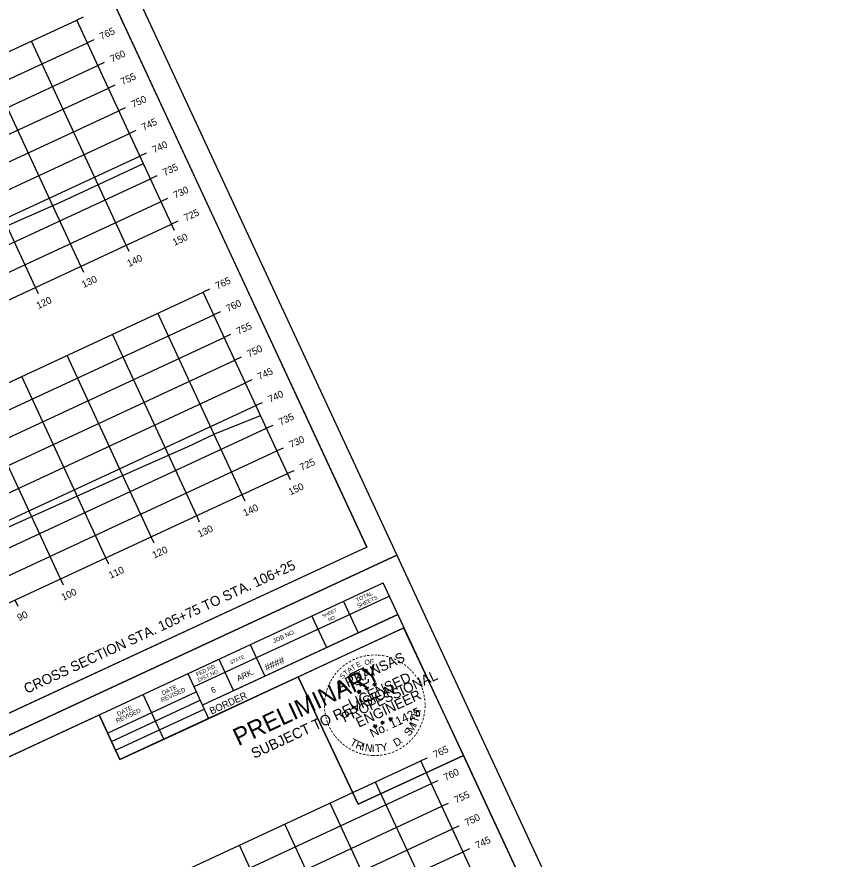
# Model space of a CAD drawing. Extents: x 1354696 to 1366163, y 660729 to 670380.
# Drawn here: x 1355461.4 to 1355627.1, y 664178.5 to 664346.9 of the extents above; entities that cross this region are included whole.
import ezdxf

# ---------------------------------------------------------------- set-up
doc = ezdxf.new("R2010")
doc.units = 0
for name, color, linetype in [('R_Axis', 7, 'Continuous'), ('R_Axis Annot', 7, 'Continuous'), ('R_Border', 7, 'Continuous'), ('R_Border PE', 7, 'Continuous'), ('R_Border Prem', 7, 'Continuous'), ('R_Draft', 7, 'Continuous'), ('R_Exist Surface', 7, 'Continuous'), ('R_Grid', 7, 'Continuous'), ('R_No Plot', 7, 'Continuous')]:
    doc.layers.add(name, color=color, linetype=linetype)

msp = doc.modelspace()

# ---------------------------------------------------------------- linework, layer by layer
at = {"layer": 'R_Axis'}
for p, q in [((1355474.6, 664346.89), (1355473.33, 664346.3)), ((1355492.28, 664305.49), (1355473.33, 664346.3)), ((1355476.71, 664342.36), (1355475.44, 664341.77)), ((1355478.81, 664337.82), (1355477.54, 664337.23)), ((1355480.92, 664333.29), (1355479.65, 664332.7)), ((1355483.02, 664328.75), (1355481.75, 664328.16)), ((1355485.13, 664324.22), (1355483.86, 664323.63)), ((1355487.23, 664319.68), (1355485.96, 664319.09)), ((1355489.34, 664315.15), (1355488.07, 664314.56)), ((1355491.45, 664310.61), (1355490.18, 664310.02)), ((1355493.55, 664306.07), (1355492.28, 664305.49)), ((1355220.18, 664179.15), (1355492.28, 664305.49)), ((1355492.87, 664304.22), (1355492.28, 664305.49)), ((1355483.8, 664300), (1355483.21, 664301.27)), ((1355474.73, 664295.79), (1355474.14, 664297.06)), ((1355465.66, 664291.58), (1355465.07, 664292.85)), ((1355499.87, 664292.47), (1355498.6, 664291.88)), ((1355515.44, 664255.6), (1355498.6, 664291.88)), ((1355501.97, 664287.93), (1355500.7, 664287.35)), ((1355504.08, 664283.4), (1355502.81, 664282.81)), ((1355506.18, 664278.86), (1355504.91, 664278.28)), ((1355508.29, 664274.33), (1355507.02, 664273.74)), ((1355510.4, 664269.79), (1355509.13, 664269.2)), ((1355512.5, 664265.26), (1355511.23, 664264.67)), ((1355514.61, 664260.72), (1355513.34, 664260.13)), ((1355243.34, 664129.27), (1355515.44, 664255.6)), ((1355516.71, 664256.19), (1355515.44, 664255.6)), ((1355516.03, 664254.33), (1355515.44, 664255.6)), ((1355506.96, 664250.12), (1355506.37, 664251.39)), ((1355497.89, 664245.91), (1355497.3, 664247.18)), ((1355488.82, 664241.7), (1355488.23, 664242.97)), ((1355479.75, 664237.49), (1355479.16, 664238.76)), ((1355470.68, 664233.27), (1355470.09, 664234.54)), ((1355461.61, 664229.06), (1355461.02, 664230.33)), ((1355543.38, 664198.74), (1355542.11, 664198.15)), ((1355558.96, 664161.87), (1355542.11, 664198.15)), ((1355545.49, 664194.21), (1355544.22, 664193.62)), ((1355547.59, 664189.67), (1355546.32, 664189.08)), ((1355549.7, 664185.14), (1355548.43, 664184.55)), ((1355551.81, 664180.6), (1355550.54, 664180.01))]:
    msp.add_line(p, q, dxfattribs=at)
at = {"layer": 'R_Border'}
for p, q in [((1355531.28, 664240.9), (1355444.76, 664427.26)), ((1355531.28, 664240.9), (1355244.5, 664107.76)), ((1355247.82, 664100.61), (1355534.6, 664233.76)), ((1355621.12, 664047.4), (1355534.6, 664233.76)), ((1355535.84, 664231.09), (1355496.75, 664212.94)), ((1355526.62, 664230.05), (1355529.54, 664223.76)), ((1355535.83, 664231.11), (1355535.83, 664231.11)), ((1355537.52, 664227.46), (1355498.43, 664209.31)), ((1355501.12, 664210.56), (1355537.52, 664227.46)), ((1355520.32, 664227.13), (1355523.25, 664220.84)), ((1355538.76, 664224.8), (1355481.95, 664198.42)), ((1355508.01, 664221.41), (1355510.93, 664215.12)), ((1355501.71, 664218.49), (1355504.63, 664212.19)), ((1355495.51, 664215.61), (1355499.67, 664206.65)), ((1355479.48, 664203.73), (1355497.2, 664211.96)), ((1355490.73, 664202.5), (1355486.57, 664211.46)), ((1355480.26, 664202.05), (1355497.98, 664210.28)), ((1355481.08, 664200.29), (1355498.8, 664208.52)), ((1355481.95, 664198.42), (1355477.79, 664207.38))]:
    msp.add_line(p, q, dxfattribs=at)
at = {"layer": 'R_Border PE'}
for p, q in [((1355532.52, 664213.35), (1355532.77, 664213.41)), ((1355532.52, 664213.35), (1355532.88, 664213.39)), ((1355532.52, 664213.35), (1355532.79, 664213.34)), ((1355532.88, 664213.39), (1355532.73, 664213.73)), ((1355532.73, 664213.73), (1355532.88, 664213.52)), ((1355532.73, 664213.73), (1355532.8, 664213.48)), ((1355532.81, 664213.03), (1355532.88, 664213.39)), ((1355532.81, 664213.03), (1355532.92, 664213.32)), ((1355532.81, 664213.03), (1355532.83, 664213.31)), ((1355533.15, 664213.64), (1355532.88, 664213.39)), ((1355533.2, 664213.21), (1355532.88, 664213.39)), ((1355533.15, 664213.64), (1355532.91, 664213.48)), ((1355533.2, 664213.21), (1355532.92, 664213.32)), ((1355533.2, 664213.21), (1355532.96, 664213.42)), ((1355533.15, 664213.64), (1355533.01, 664213.46)), ((1355529.4, 664211.91), (1355529.65, 664211.98)), ((1355529.4, 664211.91), (1355529.76, 664211.96)), ((1355529.4, 664211.91), (1355529.67, 664211.9)), ((1355529.76, 664211.96), (1355529.61, 664212.29)), ((1355529.61, 664212.29), (1355529.76, 664212.08)), ((1355529.61, 664212.29), (1355529.68, 664212.04)), ((1355529.69, 664211.6), (1355529.76, 664211.96)), ((1355529.69, 664211.6), (1355529.8, 664211.89)), ((1355529.69, 664211.6), (1355529.71, 664211.87)), ((1355530.03, 664212.21), (1355529.76, 664211.96)), ((1355530.08, 664211.78), (1355529.76, 664211.96)), ((1355530.03, 664212.21), (1355529.79, 664212.04)), ((1355530.08, 664211.78), (1355529.8, 664211.88)), ((1355530.08, 664211.78), (1355529.84, 664211.99)), ((1355530.03, 664212.21), (1355529.89, 664212.03)), ((1355530.92, 664212.62), (1355531.16, 664212.68)), ((1355530.92, 664212.62), (1355531.28, 664212.66)), ((1355530.92, 664212.62), (1355531.18, 664212.61)), ((1355531.28, 664212.66), (1355531.13, 664212.99)), ((1355531.13, 664212.99), (1355531.28, 664212.79)), ((1355531.13, 664212.99), (1355531.19, 664212.75)), ((1355531.21, 664212.3), (1355531.28, 664212.66)), ((1355531.21, 664212.3), (1355531.31, 664212.59)), ((1355531.21, 664212.3), (1355531.22, 664212.58)), ((1355531.55, 664212.91), (1355531.28, 664212.66)), ((1355531.6, 664212.48), (1355531.28, 664212.66)), ((1355531.55, 664212.91), (1355531.31, 664212.74)), ((1355531.6, 664212.48), (1355531.31, 664212.59)), ((1355531.6, 664212.48), (1355531.35, 664212.69)), ((1355531.55, 664212.91), (1355531.41, 664212.73)), ((1355535.71, 664206.48), (1355535.96, 664206.55)), ((1355535.71, 664206.48), (1355536.07, 664206.53)), ((1355535.71, 664206.48), (1355535.97, 664206.47)), ((1355536.07, 664206.53), (1355535.92, 664206.86)), ((1355535.92, 664206.86), (1355536.07, 664206.65)), ((1355535.92, 664206.86), (1355535.99, 664206.61)), ((1355536, 664206.17), (1355536.07, 664206.53)), ((1355536, 664206.17), (1355536.1, 664206.45)), ((1355536, 664206.17), (1355536.01, 664206.44)), ((1355536.34, 664206.77), (1355536.07, 664206.53)), ((1355536.39, 664206.35), (1355536.07, 664206.53)), ((1355536.34, 664206.77), (1355536.1, 664206.61)), ((1355536.39, 664206.35), (1355536.1, 664206.45)), ((1355536.39, 664206.35), (1355536.14, 664206.55)), ((1355536.34, 664206.77), (1355536.2, 664206.6)), ((1355532.59, 664205.04), (1355532.84, 664205.11)), ((1355532.59, 664205.04), (1355532.95, 664205.09)), ((1355532.59, 664205.04), (1355532.85, 664205.03)), ((1355532.95, 664205.09), (1355532.8, 664205.42)), ((1355532.8, 664205.42), (1355532.95, 664205.21)), ((1355532.8, 664205.42), (1355532.87, 664205.17)), ((1355532.88, 664204.73), (1355532.95, 664205.09)), ((1355532.88, 664204.73), (1355532.98, 664205.02)), ((1355532.88, 664204.73), (1355532.89, 664205)), ((1355533.22, 664205.34), (1355532.95, 664205.09)), ((1355533.27, 664204.91), (1355532.95, 664205.09)), ((1355533.22, 664205.34), (1355532.98, 664205.17)), ((1355533.27, 664204.91), (1355532.98, 664205.01)), ((1355533.27, 664204.91), (1355533.02, 664205.12)), ((1355533.22, 664205.34), (1355533.08, 664205.16)), ((1355534.1, 664205.75), (1355534.35, 664205.81)), ((1355534.1, 664205.75), (1355534.46, 664205.79)), ((1355534.1, 664205.75), (1355534.37, 664205.73)), ((1355534.46, 664205.79), (1355534.31, 664206.12)), ((1355534.31, 664206.12), (1355534.46, 664205.92)), ((1355534.31, 664206.12), (1355534.38, 664205.88)), ((1355534.39, 664205.43), (1355534.46, 664205.79)), ((1355534.39, 664205.43), (1355534.5, 664205.72)), ((1355534.39, 664205.43), (1355534.4, 664205.71)), ((1355534.73, 664206.04), (1355534.46, 664205.79)), ((1355534.78, 664205.61), (1355534.46, 664205.79)), ((1355534.73, 664206.04), (1355534.49, 664205.87)), ((1355534.78, 664205.61), (1355534.5, 664205.72)), ((1355534.78, 664205.61), (1355534.54, 664205.82)), ((1355534.73, 664206.04), (1355534.59, 664205.86))]:
    msp.add_line(p, q, dxfattribs=at)
for points in [[(1355531.38, 664216.09), (1355531.39, 664216.41), (1355530.78, 664216.1), (1355530.63, 664216.76), (1355527.81, 664215.45)], [(1355527.81, 664215.45), (1355528.4, 664214.81)], [(1355529.27, 664213.46), (1355529.31, 664213.38), (1355529.83, 664213.6), (1355529.98, 664213.15), (1355531.67, 664213.93), (1355531.63, 664214.5)], [(1355532.73, 664213.73), (1355533.2, 664213.21), (1355532.52, 664213.35), (1355533.15, 664213.64), (1355532.81, 664213.03), (1355532.73, 664213.73)], [(1355529.61, 664212.29), (1355530.08, 664211.78), (1355529.4, 664211.91), (1355530.03, 664212.21), (1355529.69, 664211.6), (1355529.61, 664212.29)], [(1355531.13, 664212.99), (1355531.6, 664212.48), (1355530.92, 664212.62), (1355531.55, 664212.91), (1355531.21, 664212.3), (1355531.13, 664212.99)], [(1355535.92, 664206.86), (1355536.39, 664206.35), (1355535.71, 664206.48), (1355536.34, 664206.77), (1355536, 664206.17), (1355535.92, 664206.86)], [(1355532.8, 664205.42), (1355533.27, 664204.91), (1355532.59, 664205.04), (1355533.22, 664205.34), (1355532.88, 664204.73), (1355532.8, 664205.42)], [(1355534.31, 664206.12), (1355534.78, 664205.61), (1355534.1, 664205.75), (1355534.73, 664206.04), (1355534.39, 664205.43), (1355534.31, 664206.12)]]:
    msp.add_lwpolyline(points, dxfattribs=at)
for centre, radius in [((1355532.88, 664213.39), 0.172), ((1355532.88, 664213.39), 0.145), ((1355532.88, 664213.39), 0.116), ((1355532.88, 664213.39), 0.0991), ((1355532.88, 664213.39), 0.0747), ((1355532.88, 664213.39), 0.0495), ((1355532.88, 664213.39), 0.0296), ((1355529.76, 664211.96), 0.172), ((1355529.76, 664211.96), 0.145), ((1355529.76, 664211.96), 0.116), ((1355529.76, 664211.96), 0.0991), ((1355529.76, 664211.96), 0.0747), ((1355529.76, 664211.96), 0.0495), ((1355529.76, 664211.96), 0.0296), ((1355531.28, 664212.66), 0.172), ((1355531.28, 664212.66), 0.145), ((1355531.28, 664212.66), 0.116), ((1355531.28, 664212.66), 0.0991), ((1355531.28, 664212.66), 0.0747), ((1355531.28, 664212.66), 0.0495), ((1355531.28, 664212.66), 0.0296), ((1355536.07, 664206.53), 0.172), ((1355536.07, 664206.53), 0.145), ((1355536.07, 664206.53), 0.116), ((1355536.07, 664206.53), 0.0991), ((1355536.07, 664206.53), 0.0747), ((1355536.07, 664206.53), 0.0495), ((1355536.07, 664206.53), 0.0296), ((1355532.95, 664205.09), 0.172), ((1355532.95, 664205.09), 0.145), ((1355532.95, 664205.09), 0.116), ((1355532.95, 664205.09), 0.0991), ((1355532.95, 664205.09), 0.0747), ((1355532.95, 664205.09), 0.0495), ((1355532.95, 664205.09), 0.0296), ((1355534.46, 664205.79), 0.172), ((1355534.46, 664205.79), 0.145), ((1355534.46, 664205.79), 0.116), ((1355534.46, 664205.79), 0.0991), ((1355534.46, 664205.79), 0.0747), ((1355534.46, 664205.79), 0.0495), ((1355534.46, 664205.79), 0.0296)]:
    msp.add_circle(centre, radius, dxfattribs=at)
at = {"layer": 'R_Exist Surface'}
for points in [[(1355438.91, 664296.12), (1355469.97, 664309.79), (1355486.65, 664317.62)], [(1355456.41, 664243.48), (1355485.92, 664256.77), (1355495.47, 664260.97), (1355500.92, 664263.56), (1355510.03, 664267.25)]]:
    msp.add_lwpolyline(points, dxfattribs=at)
at = {"layer": 'R_Grid'}
for p, q in [((1355201.23, 664219.97), (1355473.33, 664346.3)), ((1355492.28, 664305.49), (1355473.33, 664346.3)), ((1355203.33, 664215.44), (1355475.44, 664341.77)), ((1355483.21, 664301.27), (1355464.26, 664342.09)), ((1355474.14, 664297.06), (1355455.19, 664337.88)), ((1355205.44, 664210.9), (1355477.54, 664337.23)), ((1355207.54, 664206.37), (1355479.65, 664332.7)), ((1355465.07, 664292.85), (1355446.12, 664333.67)), ((1355209.65, 664201.83), (1355481.75, 664328.16)), ((1355211.76, 664197.3), (1355483.86, 664323.63)), ((1355213.86, 664192.76), (1355485.96, 664319.09)), ((1355215.97, 664188.23), (1355488.07, 664314.56)), ((1355218.07, 664183.69), (1355490.18, 664310.02)), ((1355220.18, 664179.15), (1355492.28, 664305.49)), ((1355226.49, 664165.55), (1355498.6, 664291.88)), ((1355515.44, 664255.6), (1355498.6, 664291.88)), ((1355228.6, 664161.01), (1355500.7, 664287.35)), ((1355506.37, 664251.39), (1355489.53, 664287.67)), ((1355230.7, 664156.48), (1355502.81, 664282.81)), ((1355497.3, 664247.18), (1355480.46, 664283.46)), ((1355488.23, 664242.97), (1355471.39, 664279.25)), ((1355232.81, 664151.94), (1355504.91, 664278.28)), ((1355234.92, 664147.41), (1355507.02, 664273.74)), ((1355479.16, 664238.76), (1355462.32, 664275.04)), ((1355470.09, 664234.54), (1355453.25, 664270.83)), ((1355237.02, 664142.87), (1355509.13, 664269.2)), ((1355239.13, 664138.34), (1355511.23, 664264.67)), ((1355241.23, 664133.8), (1355513.34, 664260.13)), ((1355243.34, 664129.27), (1355515.44, 664255.6)), ((1355270.01, 664071.82), (1355542.11, 664198.15)), ((1355558.96, 664161.87), (1355542.11, 664198.15)), ((1355272.12, 664067.29), (1355544.22, 664193.62)), ((1355549.89, 664157.66), (1355533.04, 664193.94)), ((1355540.82, 664153.45), (1355523.97, 664189.73)), ((1355274.22, 664062.75), (1355546.32, 664189.08)), ((1355276.33, 664058.22), (1355548.43, 664184.55)), ((1355531.75, 664149.24), (1355514.9, 664185.52)), ((1355522.68, 664145.03), (1355505.83, 664181.31)), ((1355278.43, 664053.68), (1355550.54, 664180.01))]:
    msp.add_line(p, q, dxfattribs=at)
at = {"layer": 'R_No Plot'}
for p, q in [((1355234.93, 664098.93), (1355537.27, 664239.3)), ((1355234.93, 664098.93), (1355537.27, 664239.29)), ((1355526.48, 664194.34), (1355526.48, 664194.34))]:
    msp.add_line(p, q, dxfattribs=at)
for points in [[(1355145.09, 664292.42), (1355447.43, 664432.79), (1355537.27, 664239.29), (1355234.93, 664098.92)], [(1355370.15, 664392.62), (1355387.95, 664400.88), (1355392.11, 664391.92), (1355406.72, 664398.7), (1355427.76, 664408.47), (1355439.73, 664382.99), (1355460.78, 664392.76), (1355531.28, 664240.9), (1355244.5, 664107.76), (1355157.98, 664294.12)], [(1355234.93, 664098.92), (1355537.27, 664239.29), (1355627.11, 664045.79), (1355324.76, 663905.42)], [(1355517.6, 664214.97), (1355538.65, 664224.75), (1355550.62, 664199.26), (1355529.57, 664189.49)], [(1355459.99, 664199.12), (1355477.79, 664207.38), (1355481.95, 664198.42), (1355496.56, 664205.2), (1355517.6, 664214.97), (1355529.57, 664189.49), (1355550.62, 664199.26), (1355621.12, 664047.4), (1355334.34, 663914.26), (1355247.82, 664100.61)]]:
    msp.add_lwpolyline(points, close=True, dxfattribs=at)

# ---------------------------------------------------------------- texts
at = {"layer": 'R_Axis Annot'}
for s, p in [('765', (1355478.27, 664342.31)), ('760', (1355480.38, 664337.78)), ('755', (1355482.48, 664333.24)), ('750', (1355484.59, 664328.7)), ('745', (1355486.69, 664324.17)), ('740', (1355488.8, 664319.63)), ('735', (1355490.9, 664315.1)), ('730', (1355493.01, 664310.56)), ('725', (1355495.12, 664306.03)), ('150', (1355492.86, 664301.12)), ('140', (1355483.78, 664296.91)), ('130', (1355474.71, 664292.7)), ('765', (1355501.43, 664292.42)), ('120', (1355465.64, 664288.49)), ('760', (1355503.54, 664287.89)), ('755', (1355505.64, 664283.35)), ('750', (1355507.75, 664278.82)), ('745', (1355509.85, 664274.28)), ('740', (1355511.96, 664269.75)), ('735', (1355514.07, 664265.21)), ('730', (1355516.17, 664260.68)), ('725', (1355518.28, 664256.14)), ('150', (1355516.02, 664251.24)), ('140', (1355506.95, 664247.02)), ('130', (1355497.88, 664242.81)), ('120', (1355488.81, 664238.6)), ('110', (1355480.1, 664234.56)), ('100', (1355470.62, 664230.16)), ('90', (1355461.8, 664226.07)), ('765', (1355544.95, 664198.7)), ('760', (1355547.05, 664194.16)), ('755', (1355549.16, 664189.63)), ('750', (1355551.26, 664185.09)), ('745', (1355553.37, 664180.56))]:
    msp.add_text(s, height=1.4, rotation=24.9042, dxfattribs=at).set_placement(p)
at = {"layer": 'R_Border'}
for s, height, p in [('TOTAL', 0.782, (1355529.37, 664229.92)), ('SHEETS', 0.782, (1355529.61, 664228.73)), ('SHEET', 0.684, (1355522.55, 664226.75)), ('NO.', 0.684, (1355523.75, 664226.01)), ('JOB NO.', 0.879, (1355512.74, 664221.67)), ('STATE', 0.684, (1355504.13, 664217.45)), ('####', 1.4, (1355511.25, 664216.08)), ('FED.RD.', 0.782, (1355497.39, 664215.07)), ('DIST.NO.', 0.782, (1355497.71, 664213.92)), ('ARK.', 1.172, (1355505.61, 664214.04)), ('DATE', 0.879, (1355490.54, 664211.25)), ('REVISED', 0.879, (1355490.33, 664209.85)), ('BORDER', 1.4, (1355500.27, 664207.4)), ('6', 1.17, (1355500.48, 664211.65)), ('REVISED', 0.879, (1355481.39, 664205.7)), ('DATE', 0.879, (1355481.6, 664207.1))]:
    msp.add_text(s, height=height, rotation=24.9042, dxfattribs=at).set_placement(p)
at = {"layer": 'R_Border PE'}
for s, height, rotation, p in [('ARKANSAS', 2, 24.9042, (1355525.91, 664212.05)), ('-', 1.6, 30.801, (1355527.94, 664217.32)), ('-', 1.6, 25.0904, (1355528.61, 664217.71)), ('-', 1.6, 22.6472, (1355529.27, 664218)), ('-', 1.6, 17.0659, (1355529.97, 664218.26)), ('-', 1.6, 12.1091, (1355530.67, 664218.46)), ('O', 1, 15.3557, (1355530.98, 664217.28)), ('-', 1.6, 7.2404, (1355531.31, 664218.59)), ('F', 1, 4.9748, (1355531.94, 664217.48)), ('-', 1.6, 2.7593, (1355532.07, 664218.7)), ('-', 1.6, 359.0253, (1355532.75, 664218.72)), ('-', 1.6, 354.5451, (1355533.4, 664218.7)), ('-', 1.6, 350.7668, (1355534.13, 664218.65)), ('-', 1.6, 345.4339, (1355534.87, 664218.52)), ('-', 1.6, 340.4828, (1355535.61, 664218.33)), ('-', 1.6, 334.7839, (1355536.36, 664218.07)), ('-', 1.6, 331.5563, (1355537.09, 664217.74)), ('-', 1.6, 44.0802, (1355526.2, 664215.94)), ('-', 1.6, 38.5343, (1355526.77, 664216.48)), ('-', 1.6, 35.1235, (1355527.32, 664216.91)), ('A', 1, 36.1173, (1355527.78, 664215.72)), ('T', 1, 30.9269, (1355528.48, 664216.23)), ('E', 1, 25.7365, (1355529.44, 664216.8)), ('-', 1.4, 328.5795, (1355537.77, 664217.43)), ('-', 1.6, 324.5725, (1355538.32, 664217.01)), ('-', 1.6, 319.567, (1355538.87, 664216.6)), ('-', 1.6, 315.477, (1355539.34, 664216.18)), ('-', 1.6, 58.9677, (1355524.91, 664214.29)), ('-', 1.6, 53.696, (1355525.29, 664214.88)), ('-', 1.6, 49.2114, (1355525.73, 664215.43)), ('S', 1, 46.4982, (1355526.45, 664214.46)), ('PROFESSIONAL', 2, 24.9042, (1355526.81, 664205.79)), ('T', 1, 41.3078, (1355527.14, 664215.15)), ('LICENSED', 2, 24.9042, (1355528.2, 664208.54)), ('-', 1.6, 310.0274, (1355539.8, 664215.75)), ('-', 1.6, 305.4535, (1355540.29, 664215.16)), ('-', 1.6, 301.5003, (1355540.77, 664214.54)), ('-', 1.6, 67.8664, (1355524.06, 664212.59)), ('-', 1.6, 63.8548, (1355524.28, 664213.15)), ('-', 1.6, 61.1359, (1355524.55, 664213.69)), ('DWB', 0.01, 24.9042, (1355532.87, 664213.39)), ('-', 1.6, 299.2343, (1355541.12, 664213.91)), ('-', 1.6, 294.8448, (1355541.42, 664213.35)), ('-', 1.6, 75.5183, (1355523.69, 664211.35)), ('-', 1.6, 73.3272, (1355523.85, 664211.96)), ('ENGINEER', 2, 24.9042, (1355529.69, 664204.78)), ('DWB', 0.01, 24.9042, (1355529.76, 664211.95)), ('DWB', 0.01, 24.9042, (1355531.27, 664212.65)), ('-', 1.6, 288.4214, (1355541.68, 664212.74)), ('-', 1.6, 285.8995, (1355541.89, 664212.11)), ('-', 1.6, 280.6668, (1355542.08, 664211.45)), ('-', 1.6, 87.7755, (1355523.46, 664209.36)), ('-', 1.6, 82.9748, (1355523.48, 664210.05)), ('-', 1.6, 79.1366, (1355523.56, 664210.66)), ('-', 1.6, 277.7723, (1355542.22, 664210.72)), ('-', 1.6, 272.7928, (1355542.3, 664210.02)), ('-', 1.6, 92.6784, (1355523.48, 664208.7)), ('-', 1.6, 97.2986, (1355523.55, 664208.03)), ('No. 11425', 1.757, 24.9042, (1355532.4, 664202.79)), ('H', 1.54, 79.513, (1355541.9, 664206.9)), ('-', 1.6, 263.9754, (1355542.29, 664208.49)), ('-', 1.6, 269.5239, (1355542.33, 664209.34)), ('-', 1.6, 100.3651, (1355523.67, 664207.3)), ('-', 1.6, 106.1054, (1355523.85, 664206.6)), ('DWB', 0.01, 24.9042, (1355536.06, 664206.52)), ('T', 1.54, 71.5486, (1355541.49, 664205.67)), ('-', 1.6, 256.1579, (1355542.05, 664207.03)), ('-', 1.6, 258.7494, (1355542.2, 664207.73)), ('-', 1.6, 110.0905, (1355524.07, 664205.94)), ('-', 1.6, 113.9664, (1355524.35, 664205.3)), ('-', 1.6, 119.1, (1355524.68, 664204.65)), ('DWB', 0.01, 24.9042, (1355532.94, 664205.08)), ('DWB', 0.01, 24.9042, (1355534.45, 664205.78)), ('S', 1.54, 51.8354, (1355539.78, 664202.97)), ('M', 1.54, 57.5605, (1355540.37, 664203.69)), ('I', 1.54, 67.0178, (1355541.18, 664205)), ('-', 1.6, 245.9893, (1355541.59, 664205.64)), ('-', 1.6, 250.6695, (1355541.85, 664206.32)), ('-', 1.6, 123.8521, (1355525.03, 664204.08)), ('-', 1.6, 126.6191, (1355525.46, 664203.47)), ('-', 1.6, 130.362, (1355525.86, 664203)), ('-', 1.6, 232.261, (1355540.61, 664203.85)), ('-', 1.6, 237.1533, (1355540.97, 664204.4)), ('-', 1.6, 240.6405, (1355541.29, 664204.98)), ('-', 1.6, 133.9916, (1355526.32, 664202.52)), ('-', 1.6, 138.9685, (1355526.8, 664202.08)), ('-', 1.6, 140.633, (1355527.34, 664201.65)), ('T', 1.54, 330.9447, (1355527.78, 664201.41)), ('R', 1.54, 338.9091, (1355528.91, 664200.78)), ('I', 1.54, 346.8735, (1355530.12, 664200.31)), ('N', 1.54, 351.4044, (1355530.83, 664200.12)), ('I', 1.54, 0.2645, (1355532.26, 664199.92)), ('T', 1.54, 4.7953, (1355533, 664199.9)), ('Y', 1.54, 12.7597, (1355534.29, 664200.01)), ('D', 1.54, 31.3011, (1355537.15, 664200.94)), ('.', 1.54, 38.6683, (1355538.18, 664201.56)), ('-', 1.6, 216.1899, (1355538.64, 664201.8)), ('-', 1.6, 220.3785, (1355539.22, 664202.29)), ('-', 1.6, 225.6226, (1355539.73, 664202.79)), ('-', 1.6, 229.1558, (1355540.18, 664203.3)), ('-', 1.6, 145.3513, (1355527.91, 664201.27)), ('-', 1.6, 150.7976, (1355528.51, 664200.93)), ('-', 1.6, 155.6223, (1355529.16, 664200.62)), ('-', 1.6, 159.128, (1355529.86, 664200.35)), ('-', 1.6, 163.838, (1355530.53, 664200.15)), ('-', 1.6, 198.0196, (1355535.96, 664200.37)), ('-', 1.6, 201.4224, (1355536.66, 664200.63)), ('-', 1.6, 206.4959, (1355537.33, 664200.96)), ('-', 1.6, 210.7208, (1355538.03, 664201.37)), ('-', 1.6, 169.5505, (1355531.21, 664200.01)), ('-', 1.6, 172.9939, (1355531.87, 664199.91)), ('-', 1.6, 176.4746, (1355532.53, 664199.86)), ('-', 1.6, 179.5044, (1355533.11, 664199.86)), ('-', 1.6, 183.4654, (1355533.78, 664199.89)), ('-', 1.6, 187.7024, (1355534.5, 664199.99)), ('-', 1.6, 192.4597, (1355535.21, 664200.14))]:
    msp.add_text(s, height=height, rotation=rotation, dxfattribs=at).set_placement(p)
at = {"layer": 'R_Border Prem'}
for s, height, p in [('PRELIMINARY', 3.5, (1355505.61, 664201.1)), ('SUBJECT TO REVISION', 2.0751, (1355508.78, 664198.57)), ('DWB', 0.01, (1355505.51, 664203.09))]:
    msp.add_text(s, height=height, rotation=24.9042, dxfattribs=at).set_placement(p)
at = {"layer": 'R_Draft'}
msp.add_text('CROSS SECTION STA. 105+75 TO STA. 106+25', height=2, rotation=24.9042, dxfattribs=at).set_placement((1355463.33, 664211.56))

doc.saveas('drawing.dxf')
